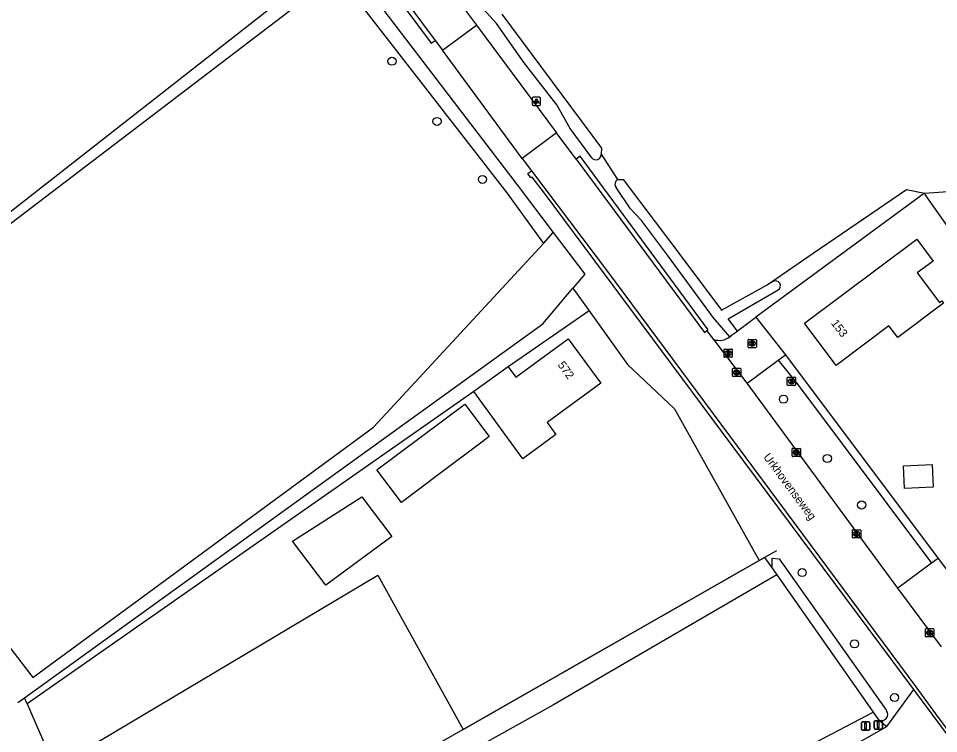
# Model space of a CAD drawing. Extents: x 164494 to 166241, y 382475 to 384494.
# Drawn here: x 164896.8 to 165007.7, y 383219 to 383305.2 of the extents above; entities that cross this region are included whole.
import ezdxf

# ---------------------------------------------------------------- set-up
doc = ezdxf.new("R2010")
doc.units = 0
for name, color, linetype in [('IMGEO_Afsluitpaal', 7, 'Continuous'), ('IMGEO_Berm_halfverhard', 7, 'Continuous'), ('IMGEO_Boom', 7, 'Continuous'), ('IMGEO_Bouwland', 7, 'Continuous'), ('IMGEO_Brandkraan', 7, 'Continuous'), ('IMGEO_Grasland_agrarisch', 7, 'Continuous'), ('IMGEO_Grasland_overig', 7, 'Continuous'), ('IMGEO_Groenvoorziening', 7, 'Continuous'), ('IMGEO_Hek', 7, 'Continuous'), ('IMGEO_Kolk', 7, 'Continuous'), ('IMGEO_Lichtpunt', 7, 'Continuous'), ('IMGEO_Loofbos', 7, 'Continuous'), ('IMGEO_Openbare_ruimte_label', 7, 'Continuous'), ('IMGEO_Pand', 7, 'Continuous'), ('IMGEO_Pand_nummerreeks', 7, 'Continuous'), ('IMGEO_Parkeervlak_open', 7, 'Continuous'), ('IMGEO_Rijbaan_lokaal_gesloten', 7, 'Continuous'), ('IMGEO_Rioolput', 7, 'Continuous'), ('IMGEO_Voetpad_halfverhard', 7, 'Continuous'), ('IMGEO_Voetpad_open', 7, 'Continuous'), ('IMGEO_Waterloop', 7, 'Continuous')]:
    doc.layers.add(name, color=color, linetype=linetype)

msp = doc.modelspace()

# ---------------------------------------------------------------- linework, layer by layer
at = {"layer": 'IMGEO_Afsluitpaal'}
for p, q in [((164998.39, 383219.47), (164998.39, 383220.27)), ((164998.39, 383220.27), (164998.39, 383219.47)), ((164998.49, 383220.37), (164999.28, 383220.37)), ((164999.28, 383220.37), (164998.49, 383220.37)), ((164999.38, 383220.27), (164999.38, 383219.47)), ((164999.38, 383219.47), (164999.38, 383220.27)), ((164999.92, 383219.61), (164999.92, 383220.41)), ((164999.92, 383220.41), (164999.92, 383219.61)), ((165000.02, 383220.51), (165000.81, 383220.51)), ((165000.81, 383220.51), (165000.02, 383220.51)), ((165000.91, 383220.41), (165000.91, 383219.61)), ((165000.91, 383219.61), (165000.91, 383220.41)), ((164999.28, 383219.37), (164998.49, 383219.37)), ((164998.49, 383219.37), (164999.28, 383219.37)), ((165000.81, 383219.51), (165000.02, 383219.51)), ((165000.02, 383219.51), (165000.81, 383219.51))]:
    msp.add_line(p, q, dxfattribs=at)
for points in [[(164998.81, 383220.24), (164998.96, 383220.24), (164998.96, 383219.49), (164998.81, 383219.49), (164998.81, 383220.24)], [(165000.34, 383220.39), (165000.49, 383220.39), (165000.49, 383219.64), (165000.34, 383219.64), (165000.34, 383220.39)]]:
    msp.add_lwpolyline(points, dxfattribs=at)
for centre, start, end in [((164998.49, 383220.27), 90, 180), ((164998.49, 383220.27), 90, 180), ((164999.28, 383220.27), 0, 90), ((164999.28, 383220.27), 360, 90), ((165000.02, 383220.41), 90, 180), ((165000.02, 383220.41), 90, 180), ((165000.81, 383220.41), 0, 90), ((165000.81, 383220.41), 360, 90), ((164998.49, 383219.47), 180, 270), ((164998.49, 383219.47), 180, 270), ((164999.28, 383219.47), 270, 0), ((164999.28, 383219.47), 270, 0), ((165000.02, 383219.61), 180, 270), ((165000.02, 383219.61), 180, 270), ((165000.81, 383219.61), 270, 0), ((165000.81, 383219.61), 270, 0)]:
    msp.add_arc(centre, 0.1, start, end, dxfattribs=at)
at = {"layer": 'IMGEO_Berm_halfverhard'}
for points in [[(164898.89, 383366.18), (164946.53, 383302.21), (164947.02, 383302.56)], [(164979.77, 383267.57), (164979.9, 383267.67), (164964.47, 383288.59), (164963.99, 383288.23)], [(165004.7, 383224.27), (164981.5, 383255.45), (164960.2, 383284.12), (164958.68, 383286.07), (164958.55, 383285.99), (164958.17, 383286.49), (164958.62, 383286.84)]]:
    msp.add_lwpolyline(points, dxfattribs=at)
at = {"layer": 'IMGEO_Boom'}
for centre in [(164941.79, 383300.04), (164947.22, 383292.78), (164952.7, 383285.79), (164988.99, 383259.29), (164994.27, 383252.14), (164998.41, 383246.53), (164991.24, 383238.38), (164997.55, 383229.79), (165002.38, 383223.31)]:
    msp.add_circle(centre, 0.489, dxfattribs=at)
at = {"layer": 'IMGEO_Bouwland'}
msp.add_lwpolyline([(164967.02, 383288.82), (164968.99, 383285.78)], dxfattribs=at)
at = {"layer": 'IMGEO_Brandkraan'}
for p, q in [((164989.45, 383261.01), (164989.45, 383261.87)), ((164989.52, 383261.94), (164990.38, 383261.94)), ((164989.96, 383261.16), (164989.93, 383261.16)), ((164989.94, 383261.72), (164989.96, 383261.72)), ((164990.45, 383261.87), (164990.45, 383261.01)), ((164990.38, 383260.94), (164989.52, 383260.94))]:
    msp.add_line(p, q, dxfattribs=at)
for points in [[(164989.45, 383261.01), (164989.45, 383261.87)], [(164989.52, 383261.94), (164990.38, 383261.94)], [(164989.8, 383261.64), (164989.8, 383261.24), (164990.01, 383261.24)], [(164990.03, 383261.64), (164989.8, 383261.64)], [(164989.97, 383261.56), (164989.92, 383261.56), (164989.92, 383261.48)], [(164989.92, 383261.48), (164989.97, 383261.48)], [(164989.98, 383261.41), (164989.92, 383261.41), (164989.92, 383261.33)], [(164989.92, 383261.33), (164989.98, 383261.33)], [(164990.45, 383261.87), (164990.45, 383261.01)], [(164990.38, 383260.94), (164989.52, 383260.94)]]:
    msp.add_lwpolyline(points, dxfattribs=at)
for centre, radius, start, end in [((164989.52, 383261.87), 0.0765, 91.552, 178.448), ((164989.52, 383261.87), 0.0765, 91.552, 178.448), ((164989.98, 383261.52), 0.0379, 267.8285, 90.9355), ((164989.98, 383261.37), 0.0404, 269.8759, 90.5077), ((164990.01, 383261.49), 0.251, 268.6676, 293.5347), ((164990.03, 383261.5), 0.145, 59.4692, 91.5367), ((164990.06, 383261.54), 0.0922, 285.5137, 58.1501), ((164990.06, 383261.35), 0.105, 301.3115, 78.989), ((164990.37, 383261.87), 0.0765, 1.552, 88.448), ((164990.37, 383261.87), 0.0765, 1.552, 88.448), ((164989.52, 383261.02), 0.0765, 181.552, 268.448), ((164989.52, 383261.02), 0.0765, 181.552, 268.448), ((164990.37, 383261.02), 0.0765, 271.552, 358.448), ((164990.37, 383261.02), 0.0765, 271.552, 358.448)]:
    msp.add_arc(centre, radius, start, end, dxfattribs=at)
for centre, major_axis, ratio, start_param, end_param in [((164989.94, 383261.44), (-0.387, 0.002), 0.722429, 4.712389, 7.853982), ((164989.96, 383261.44), (-0.39, 0.002), 0.717154, 1.570796, 4.712389)]:
    msp.add_ellipse(centre, major_axis=major_axis, ratio=ratio, start_param=start_param, end_param=end_param, dxfattribs=at)
at = {"layer": 'IMGEO_Grasland_agrarisch'}
for points in [[(164834.1, 383296.91), (164881.99, 383247.23), (164898.48, 383225.71), (164939.55, 383255.93), (164960.04, 383278.08)], [(164907.46, 383171.6), (164949.35, 383194.41), (164992.36, 383217.63), (164999.81, 383221.56)]]:
    msp.add_lwpolyline(points, dxfattribs=at)
at = {"layer": 'IMGEO_Grasland_overig'}
for points in [[(164987.03, 383273.08), (164992.55, 383276.9), (165003.84, 383284.58), (165005.99, 383284.12)], [(165005.99, 383284.12), (165013.31, 383284.65), (165024.64, 383268.79)], [(165005.99, 383284.12), (164985.66, 383269.16)], [(165029.15, 383261.42), (165023.92, 383258.65), (165006.08, 383283.99), (165005.99, 383284.12)], [(164897.51, 383223.29), (164959.97, 383268.39), (164963.61, 383272.68)], [(164963.61, 383272.68), (164965.56, 383269.95)], [(164965.56, 383269.95), (164955.81, 383263.21)], [(164951.66, 383260.2), (164937.06, 383250), (164897.83, 383222.54)], [(164986.06, 383239.83), (164986.71, 383240.2), (164987.61, 383238.93)], [(164950.37, 383219.45), (164986.06, 383239.83)], [(164901.16, 383214.86), (164940.07, 383238.06), (164950.37, 383219.45)], [(164988.18, 383238.12), (164961.27, 383222.45), (164903.86, 383190.4)], [(164950.37, 383219.45), (164903.43, 383192.65)]]:
    msp.add_lwpolyline(points, dxfattribs=at)
at = {"layer": 'IMGEO_Groenvoorziening'}
for points in [[(164961.24, 383279.38), (164965.05, 383274.38), (164963.61, 383272.68)], [(164965.56, 383269.95), (164970.17, 383263.46), (164975.85, 383258.13), (164986.06, 383239.83)], [(165000.46, 383220.63), (165001.45, 383219.83)]]:
    msp.add_lwpolyline(points, dxfattribs=at)
at = {"layer": 'IMGEO_Hek'}
for points in [[(164986.71, 383240.2), (164950.37, 383219.45), (164903.43, 383192.65)], [(164988.13, 383241.01), (164986.71, 383240.2)]]:
    msp.add_lwpolyline(points, dxfattribs=at)
at = {"layer": 'IMGEO_Kolk'}
for p, q in [((164982.84, 383262.09), (164982.84, 383262.94)), ((164982.91, 383263.01), (164983.77, 383263.01)), ((164983.33, 383262.79), (164983.35, 383262.79)), ((164983.84, 383262.94), (164983.84, 383262.09)), ((164983.77, 383262.01), (164982.91, 383262.01)), ((164983.35, 383262.23), (164983.33, 383262.23)), ((164990.04, 383252.44), (164990.04, 383253.29)), ((164990.11, 383253.36), (164990.97, 383253.36)), ((164990.97, 383252.36), (164990.11, 383252.36)), ((164990.55, 383252.58), (164990.52, 383252.58)), ((164990.53, 383253.14), (164990.55, 383253.14)), ((164991.04, 383253.29), (164991.04, 383252.44)), ((164997.3, 383242.63), (164997.3, 383243.48)), ((164997.37, 383243.55), (164998.22, 383243.55)), ((164998.3, 383243.48), (164998.3, 383242.63)), ((164998.22, 383242.55), (164997.37, 383242.55)), ((164997.81, 383242.77), (164997.78, 383242.77)), ((164997.79, 383243.33), (164997.81, 383243.33)), ((165006.12, 383230.69), (165006.12, 383231.55)), ((165006.19, 383231.62), (165007.04, 383231.62)), ((165006.6, 383231.4), (165006.63, 383231.4)), ((165007.12, 383231.55), (165007.12, 383230.69)), ((165007.04, 383230.62), (165006.19, 383230.62)), ((165006.63, 383230.84), (165006.6, 383230.84))]:
    msp.add_line(p, q, dxfattribs=at)
for points in [[(164982.84, 383262.09), (164982.84, 383262.94)], [(164982.91, 383263.01), (164983.77, 383263.01)], [(164983.16, 383262.71), (164983.28, 383262.71), (164983.28, 383262.56), (164983.41, 383262.71), (164983.58, 383262.71), (164983.43, 383262.56), (164983.58, 383262.31), (164983.43, 383262.31), (164983.35, 383262.48), (164983.28, 383262.41), (164983.28, 383262.31), (164983.16, 383262.31), (164983.16, 383262.71)], [(164983.84, 383262.94), (164983.84, 383262.09)], [(164983.77, 383262.01), (164982.91, 383262.01)], [(164990.04, 383252.44), (164990.04, 383253.29)], [(164990.11, 383253.36), (164990.97, 383253.36)], [(164990.97, 383252.36), (164990.11, 383252.36)], [(164990.36, 383253.06), (164990.48, 383253.06), (164990.48, 383252.91), (164990.61, 383253.06), (164990.78, 383253.06), (164990.63, 383252.91), (164990.78, 383252.66), (164990.63, 383252.66), (164990.55, 383252.83), (164990.48, 383252.76), (164990.48, 383252.66), (164990.36, 383252.66), (164990.36, 383253.06)], [(164991.04, 383253.29), (164991.04, 383252.44)], [(164997.3, 383242.63), (164997.3, 383243.48)], [(164997.37, 383243.55), (164998.22, 383243.55)], [(164998.3, 383243.48), (164998.3, 383242.63)], [(164998.22, 383242.55), (164997.37, 383242.55)], [(164997.62, 383243.25), (164997.74, 383243.25), (164997.74, 383243.1), (164997.87, 383243.25), (164998.04, 383243.25), (164997.89, 383243.1), (164998.04, 383242.85), (164997.89, 383242.85), (164997.81, 383243.02), (164997.74, 383242.95), (164997.74, 383242.85), (164997.62, 383242.85), (164997.62, 383243.25)], [(165006.12, 383230.69), (165006.12, 383231.55)], [(165006.19, 383231.62), (165007.04, 383231.62)], [(165006.44, 383231.32), (165006.56, 383231.32), (165006.56, 383231.17), (165006.69, 383231.32), (165006.85, 383231.32), (165006.71, 383231.17), (165006.86, 383230.92), (165006.71, 383230.92), (165006.62, 383231.08), (165006.56, 383231.02), (165006.56, 383230.92), (165006.44, 383230.92), (165006.44, 383231.32)], [(165007.12, 383231.55), (165007.12, 383230.69)], [(165007.04, 383230.62), (165006.19, 383230.62)]]:
    msp.add_lwpolyline(points, dxfattribs=at)
for centre, start, end in [((164982.92, 383262.94), 91.552, 178.448), ((164982.92, 383262.94), 91.552, 178.448), ((164983.76, 383262.94), 1.552, 88.448), ((164983.76, 383262.94), 1.552, 88.448), ((164982.92, 383262.09), 181.552, 268.448), ((164982.92, 383262.09), 181.552, 268.448), ((164983.76, 383262.09), 271.552, 358.448), ((164983.76, 383262.09), 271.552, 358.448), ((164990.11, 383253.29), 91.552, 178.448), ((164990.11, 383253.29), 91.552, 178.448), ((164990.11, 383252.44), 181.552, 268.448), ((164990.11, 383252.44), 181.552, 268.448), ((164990.96, 383253.29), 1.552, 88.448), ((164990.96, 383253.29), 1.552, 88.448), ((164990.96, 383252.44), 271.552, 358.448), ((164990.96, 383252.44), 271.552, 358.448), ((164997.37, 383243.48), 91.552, 178.448), ((164997.37, 383243.48), 91.552, 178.448), ((164998.22, 383243.48), 1.552, 88.448), ((164998.22, 383243.48), 1.552, 88.448), ((164997.37, 383242.63), 181.552, 268.448), ((164997.37, 383242.63), 181.552, 268.448), ((164998.22, 383242.63), 271.552, 358.448), ((164998.22, 383242.63), 271.552, 358.448), ((165006.19, 383231.54), 91.552, 178.448), ((165006.19, 383231.54), 91.552, 178.448), ((165007.04, 383231.54), 1.552, 88.448), ((165007.04, 383231.54), 1.552, 88.448), ((165006.19, 383230.7), 181.552, 268.448), ((165006.19, 383230.7), 181.552, 268.448), ((165007.04, 383230.7), 271.552, 358.448), ((165007.04, 383230.7), 271.552, 358.448)]:
    msp.add_arc(centre, 0.0765, start, end, dxfattribs=at)
for centre, major_axis, ratio, start_param, end_param in [((164983.33, 383262.51), (-0.387, 0.002), 0.722429, 4.712389, 7.853982), ((164983.35, 383262.51), (-0.39, 0.002), 0.717154, 1.570796, 4.712389), ((164990.53, 383252.86), (-0.387, 0.002), 0.722429, 4.712389, 7.853982), ((164990.55, 383252.86), (-0.39, 0.002), 0.717154, 1.570796, 4.712389), ((164997.78, 383243.05), (-0.387, 0.002), 0.722429, 4.712389, 7.853982), ((164997.81, 383243.05), (-0.39, 0.002), 0.717154, 1.570796, 4.712389), ((165006.6, 383231.12), (-0.387, 0.002), 0.722429, 4.712389, 7.853982), ((165006.63, 383231.12), (-0.39, 0.002), 0.717154, 1.570796, 4.712389)]:
    msp.add_ellipse(centre, major_axis=major_axis, ratio=ratio, start_param=start_param, end_param=end_param, dxfattribs=at)
at = {"layer": 'IMGEO_Lichtpunt'}
for p, q in [((164958.71, 383295.62), (164958.71, 383294.81)), ((164958.71, 383295.62), (164958.71, 383294.81)), ((164959.61, 383295.71), (164958.81, 383295.71)), ((164959.61, 383295.71), (164958.81, 383295.71)), ((164959.71, 383294.81), (164959.71, 383295.62)), ((164959.71, 383294.81), (164959.71, 383295.62)), ((164958.81, 383294.71), (164959.61, 383294.71)), ((164958.81, 383294.71), (164959.61, 383294.71))]:
    msp.add_line(p, q, dxfattribs=at)
for points in [[(164959.09, 383295.28), (164959.12, 383295.25), (164958.94, 383294.99), (164958.9, 383295.02), (164959.09, 383295.28)], [(164959.19, 383295.23), (164959.23, 383295.23), (164959.23, 383294.91), (164959.19, 383294.91), (164959.19, 383295.23)], [(164959.3, 383295.25), (164959.34, 383295.28), (164959.52, 383295.02), (164959.48, 383294.99), (164959.3, 383295.25)]]:
    msp.add_lwpolyline(points, dxfattribs=at)
msp.add_circle((164959.21, 383295.41), 0.0994, dxfattribs=at)
for centre, start, end in [((164958.81, 383295.62), 90, 180), ((164958.81, 383295.62), 90, 180), ((164959.61, 383295.62), 0, 90), ((164959.61, 383295.62), 0, 90), ((164958.81, 383294.81), 180, 270), ((164958.81, 383294.81), 180, 270), ((164959.61, 383294.81), 270, 0), ((164959.61, 383294.81), 270, 360)]:
    msp.add_arc(centre, 0.0946, start, end, dxfattribs=at)
at = {"layer": 'IMGEO_Loofbos'}
for points in [[(164896.71, 383222.7), (164897.51, 383223.29)], [(164897.83, 383222.54), (164897.51, 383223.29)], [(164897.83, 383222.54), (164900.71, 383215.89), (164901.16, 383214.86)]]:
    msp.add_lwpolyline(points, dxfattribs=at)
at = {"layer": 'IMGEO_Pand'}
for points in [[(165002.76, 383266.71), (165001.69, 383268.12), (164995.36, 383263.35), (164991.51, 383268.45), (165005.07, 383278.57), (165007.02, 383275.95), (165005.1, 383274.51), (165007.81, 383270.93), (165008.09, 383271.14), (165008.29, 383270.88), (165002.76, 383266.71)], [(164955.81, 383263.21), (164956.74, 383261.95), (164963.02, 383266.55), (164966.97, 383261.24), (164960.49, 383256.48), (164961.55, 383255.02), (164957.55, 383252.11), (164954.88, 383255.78), (164951.66, 383260.2)], [(164955.81, 383263.21), (164951.66, 383260.2)], [(164942.93, 383246.82), (164939.97, 383250.76), (164950.58, 383258.7), (164953.52, 383254.79), (164952.62, 383254.12), (164947.54, 383250.29), (164942.93, 383246.82)], [(165003.56, 383248.53), (165003.45, 383251.26), (165006.92, 383251.41), (165007.04, 383248.68), (165003.56, 383248.53)], [(164941.79, 383242.72), (164933.81, 383236.88), (164929.82, 383242.15), (164938.15, 383247.53), (164941.79, 383242.72)]]:
    msp.add_lwpolyline(points, dxfattribs=at)
at = {"layer": 'IMGEO_Parkeervlak_open'}
for points in [[(164983.43, 383267.51), (164983.55, 383267.6), (164985.66, 383269.16)], [(164985.66, 383269.16), (164989.23, 383264.62)], [(164982.74, 383267.01), (164983.43, 383267.51)], [(164984.61, 383261.22), (164988.36, 383263.98)], [(165007.64, 383240.09), (165012.9, 383233.07)], [(165006.84, 383239.5), (165002.79, 383236.5)]]:
    msp.add_lwpolyline(points, dxfattribs=at)
for centre, radius, start, end in [((164981.26, 383268.44), 2.06, 251.1603, 307.8319), ((164981.4, 383268.28), 1.85, 307.2472, 316.4987)]:
    msp.add_arc(centre, radius, start, end, dxfattribs=at)
at = {"layer": 'IMGEO_Rijbaan_lokaal_gesloten'}
for points in [[(164867.99, 383408.67), (164897.53, 383369.01), (164899.31, 383366.62), (164947.02, 383302.56)], [(164949.57, 383307.63), (164951.99, 383304.39)], [(164947.9, 383301.37), (164951.99, 383304.39)], [(164951.99, 383304.39), (164961.64, 383291.4)], [(164947.02, 383302.56), (164947.9, 383301.37)], [(164957.5, 383288.33), (164947.9, 383301.37)], [(164961.64, 383291.4), (164957.5, 383288.33)], [(164963.99, 383288.23), (164961.64, 383291.4)], [(164957.5, 383288.33), (164958.62, 383286.84)], [(164963.99, 383288.23), (164979.46, 383267.35), (164979.77, 383267.57)], [(164958.62, 383286.84), (164967.78, 383274.69), (165004.94, 383224.6), (165007.31, 383221.33), (165010.83, 383216.64), (165074.54, 383131.07)], [(164980.6, 383266.49), (164979.77, 383267.57)], [(164984.61, 383261.22), (164980.6, 383266.49)], [(165002.79, 383236.5), (164984.61, 383261.22)], [(165008.04, 383229.43), (165002.79, 383236.5)]]:
    msp.add_lwpolyline(points, dxfattribs=at)
at = {"layer": 'IMGEO_Rioolput'}
for p, q in [((164984.72, 383265.58), (164984.72, 383266.43)), ((164984.79, 383266.5), (164985.64, 383266.5)), ((164985.2, 383266.28), (164985.23, 383266.28)), ((164985.23, 383265.72), (164985.2, 383265.72)), ((164985.72, 383266.43), (164985.72, 383265.58)), ((164981.82, 383264.42), (164981.82, 383265.27)), ((164981.89, 383265.34), (164982.74, 383265.34)), ((164982.33, 383264.56), (164982.3, 383264.56)), ((164982.31, 383265.12), (164982.33, 383265.12)), ((164982.82, 383265.27), (164982.82, 383264.42)), ((164985.64, 383265.5), (164984.79, 383265.5)), ((164982.74, 383264.34), (164981.89, 383264.34))]:
    msp.add_line(p, q, dxfattribs=at)
for points in [[(164984.72, 383265.58), (164984.72, 383266.43)], [(164984.79, 383266.5), (164985.64, 383266.5)], [(164985.31, 383266.2), (164985.05, 383266.2), (164985.05, 383265.8)], [(164985.05, 383265.8), (164985.18, 383265.8), (164985.18, 383265.97), (164985.19, 383265.97)], [(164985.23, 383266.12), (164985.18, 383266.12), (164985.18, 383266.04)], [(164985.18, 383266.04), (164985.23, 383266.04)], [(164985.23, 383265.94), (164985.31, 383265.8), (164985.45, 383265.8), (164985.38, 383265.93)], [(164985.72, 383266.43), (164985.72, 383265.58)], [(164981.82, 383264.42), (164981.82, 383265.27)], [(164981.89, 383265.34), (164982.74, 383265.34)], [(164982.41, 383265.04), (164982.15, 383265.04), (164982.15, 383264.64)], [(164982.15, 383264.64), (164982.28, 383264.64), (164982.28, 383264.81), (164982.29, 383264.81)], [(164982.33, 383264.96), (164982.28, 383264.96), (164982.28, 383264.88)], [(164982.28, 383264.88), (164982.33, 383264.88)], [(164982.34, 383264.78), (164982.41, 383264.64), (164982.55, 383264.64), (164982.48, 383264.77)], [(164982.82, 383265.27), (164982.82, 383264.42)], [(164985.64, 383265.5), (164984.79, 383265.5)], [(164982.74, 383264.34), (164981.89, 383264.34)]]:
    msp.add_lwpolyline(points, dxfattribs=at)
for centre, radius, start, end in [((164984.79, 383266.43), 0.0765, 91.552, 178.448), ((164984.79, 383266.43), 0.0765, 91.552, 178.448), ((164985.19, 383265.91), 0.0533, 26.0293, 88.6989), ((164985.24, 383266.03), 0.0964, 77.0061, 93.1865), ((164985.21, 383266.23), 0.19, 274.7715, 282.9687), ((164985.25, 383266.08), 0.0378, 276.6634, 79.6772), ((164985.3, 383266.09), 0.109, 350.3612, 89.416), ((164985.3, 383266.09), 0.112, 277.5842, 350.9817), ((164985.29, 383265.88), 0.108, 29.5134, 73.7905), ((164985.64, 383266.43), 0.0765, 1.552, 88.448), ((164985.64, 383266.43), 0.0765, 1.552, 88.448), ((164981.89, 383265.27), 0.0765, 91.552, 178.448), ((164981.89, 383265.27), 0.0765, 91.552, 178.448), ((164982.29, 383264.75), 0.0533, 26.0293, 88.6989), ((164982.34, 383264.87), 0.0964, 77.0061, 93.1865), ((164982.31, 383265.07), 0.19, 274.7715, 282.9687), ((164982.35, 383264.92), 0.0378, 276.6634, 79.6772), ((164982.41, 383264.93), 0.109, 350.3612, 89.416), ((164982.4, 383264.93), 0.112, 277.5842, 350.9817), ((164982.39, 383264.72), 0.108, 29.5134, 73.7905), ((164982.74, 383265.27), 0.0765, 1.552, 88.448), ((164982.74, 383265.27), 0.0765, 1.552, 88.448), ((164984.79, 383265.58), 0.0765, 181.552, 268.448), ((164984.79, 383265.58), 0.0765, 181.552, 268.448), ((164985.64, 383265.58), 0.0765, 271.552, 358.448), ((164985.64, 383265.58), 0.0765, 271.552, 358.448), ((164981.89, 383264.42), 0.0765, 181.552, 268.448), ((164981.89, 383264.42), 0.0765, 181.552, 268.448), ((164982.74, 383264.42), 0.0765, 271.552, 358.448), ((164982.74, 383264.42), 0.0765, 271.552, 358.448)]:
    msp.add_arc(centre, radius, start, end, dxfattribs=at)
for centre, major_axis, ratio, start_param, end_param in [((164985.2, 383266), (-0.387, 0.002), 0.722429, 4.712389, 7.853982), ((164985.23, 383266), (-0.39, 0.002), 0.717154, 1.570796, 4.712389), ((164982.3, 383264.84), (-0.387, 0.002), 0.722429, 4.712389, 7.853982), ((164982.33, 383264.84), (-0.39, 0.002), 0.717154, 1.570796, 4.712389)]:
    msp.add_ellipse(centre, major_axis=major_axis, ratio=ratio, start_param=start_param, end_param=end_param, dxfattribs=at)
at = {"layer": 'IMGEO_Voetpad_halfverhard'}
for points in [[(165001.45, 383219.83), (165002.52, 383221.3), (165004.7, 383224.27)], [(165010.16, 383216.93), (165004.7, 383224.27)], [(164897.42, 383160.93), (164911.35, 383169.35), (164968.99, 383201.4), (165001.45, 383219.83)]]:
    msp.add_lwpolyline(points, dxfattribs=at)
at = {"layer": 'IMGEO_Voetpad_open'}
for points in [[(164988.36, 383263.98), (164989.23, 383264.62)], [(164989.23, 383264.62), (164989.47, 383264.32), (165007.64, 383240.09)], [(164988.36, 383263.98), (164990.66, 383261.09), (165006.84, 383239.5)], [(165007.64, 383240.09), (165006.84, 383239.5)]]:
    msp.add_lwpolyline(points, dxfattribs=at)
at = {"layer": 'IMGEO_Waterloop'}
for points in [[(164896.81, 383364), (164902.87, 383356.58), (164911.4, 383344.92), (164923.31, 383329.12), (164956.87, 383285.13), (164961.24, 383279.38)], [(164965.88, 383288.41), (164963.27, 383291.95), (164961.67, 383294.77), (164957.74, 383299.84), (164954.38, 383304.59), (164952.8, 383306.38), (164950.61, 383309.66), (164948.93, 383311.65), (164947.06, 383314.63), (164930.65, 383337.39), (164931.46, 383338.02)], [(164934.11, 383311.92), (164875, 383265.61), (164875.47, 383265.01), (164935.17, 383310.55)], [(164935.17, 383310.55), (164955.63, 383284.19), (164960.04, 383278.08)], [(164955.05, 383305.73), (164967.06, 383289.54), (164967.02, 383288.82)], [(164968.99, 383285.78), (164969.68, 383285.79), (164976.01, 383277.38), (164981.53, 383270.04), (164987.03, 383273.08)], [(164982.52, 383266.81), (164980.57, 383269.11), (164974.99, 383276.64), (164971.88, 383280.83), (164970.54, 383282.23), (164968.81, 383284.8)], [(164960.04, 383278.08), (164961.24, 383279.38)], [(164987.76, 383273.49), (164987.03, 383273.08)], [(164983.43, 383267.51), (164982.34, 383268.96), (164988.34, 383272.47)], [(164987.61, 383238.93), (164987.64, 383240.13), (164988.45, 383240.02), (165001.41, 383221.73)], [(164987.61, 383238.93), (164988.18, 383238.12)], [(164988.18, 383238.12), (164999.17, 383222.48), (164999.81, 383221.56)], [(164999.81, 383221.56), (165000.46, 383220.63)]]:
    msp.add_lwpolyline(points, dxfattribs=at)
for centre, radius, start, end in [((164966.38, 383288.78), 0.634, 216.7507, 3.4332), ((164969.36, 383285.2), 0.684, 122.6776, 216.1467), ((164988.04, 383272.97), 0.589, 300.2419, 119.0305), ((165000.83, 383221.27), 0.737, 240.1608, 37.9146)]:
    msp.add_arc(centre, radius, start, end, dxfattribs=at)

# ---------------------------------------------------------------- texts
at = {"layer": 'IMGEO_Openbare_ruimte_label'}
msp.add_text('Urkhovenseweg', height=1, rotation=306.5834, dxfattribs=at).set_placement((164986.51, 383252.31))
at = {"layer": 'IMGEO_Pand_nummerreeks'}
for s, rotation, p in [('153', 307.0472, (164994.67, 383268.44)), ('572', 306.0339, (164961.72, 383263.41))]:
    msp.add_text(s, height=1, rotation=rotation, dxfattribs=at).set_placement(p)

doc.saveas('drawing.dxf')
